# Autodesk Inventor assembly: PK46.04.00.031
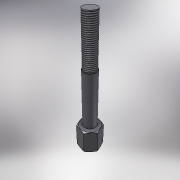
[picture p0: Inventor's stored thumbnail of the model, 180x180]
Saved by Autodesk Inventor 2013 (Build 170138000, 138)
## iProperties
Created: 2005-04
Part Number: PK46.04.00.031
Document SubType Name: Assembly
Designer: salex
Manufacturer: Standard
Standards Organization: Custom
Author: salex
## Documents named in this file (3)
- C:\Product Design Suite 2013 Test Drive\Dynamic Simulation\Workspace\Assy, Chassis, Front\PK46.04.00.031.iam
- C:\Product Design Suite 2013 Test Drive\Dynamic Simulation\Workspace\Assy, Chassis, Front\027.15.23.127.ipt
- C:\Product Design Suite 2013 Test Drive\Dynamic Simulation\Workspace\Assy, Chassis, Front\027.13.15.227.ipt
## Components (2 placed, 2 different names)
1. 027.15.23.127:1 — Вставка:1
2. 027.13.15.227:1 — Вставка:1
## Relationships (1: Insert 1)
- Вставка:1 [Insert]: 027.15.23.127:1 ↔ 027.13.15.227:1
